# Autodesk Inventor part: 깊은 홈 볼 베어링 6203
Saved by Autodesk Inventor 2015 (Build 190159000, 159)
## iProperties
Created: 2026-05
Part Number: 깊은 홈 볼 베어링 6203
Material: 일반
Document SubType Name: Modeling
Designer: 104
Density: 1 g/cm^3
Appearance: 기본값
Author: 104
Author: jhkim
Description: 깊은 그루브 볼 베어링
Creation Date: 2026-04-27
Sending System: Autodesk Inventor 2027
Preprocessor: ST-DEVELOPER v20.1
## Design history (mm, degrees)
node "깊은 홈 볼 베어링 62031"
body "Solid1"
node "Solid1_1"
node "Solid1_2"
node "Solid1_3"
node "Solid1_4"
node "Solid1_5"
node "Solid1_6"
node "Solid1_7"
node "Solid1_8"
node "기준1"
node "기준2"
node "기준3"
node "기준4"
node "기준5"
node "기준6"
node "기준7"
node "기준8"
node "기준9"
